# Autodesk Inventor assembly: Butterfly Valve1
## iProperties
Shininess: 64.0
Length Units: 11269
Angle Units: 11279
Time Units: 11290
Mass Units: 11283
Length Display Precision: 3
Angle Display Precision: 2
Created: 2002-02
Part Number: Butterfly Valve1
Document SubType Name: Assembly
Designer: ***
Density: 0.0
Volumn: 0.0
Area: 0.0
PropertySet Name: Model Information
Control State: 0
Master: False
Checked Out: False
Author: ***
